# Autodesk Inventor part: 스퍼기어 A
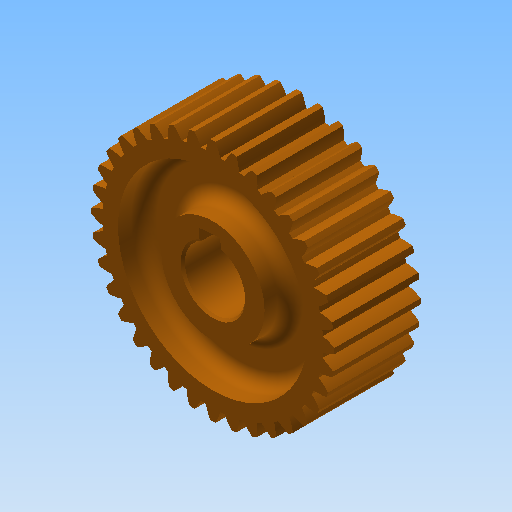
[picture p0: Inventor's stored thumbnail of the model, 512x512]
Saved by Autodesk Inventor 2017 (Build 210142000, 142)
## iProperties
Created: 2020-04
Part Number: 스퍼기어 A
Material: Steel
Document SubType Name: Modeling
Designer: mduedu
Categories: <?xml version="1.0" encoding="UTF-16"?> <MemberInstance><Categories><FamilyTemplate><FamilyTemplateParameter ValueType="xs:double" Id="1" ObjectReferenceKey="da
Density: 7.85 g/cm^3
Mass: 238.005 g
Surface Area: 130.635 cm^2
Volume: 30.3191 cm^3
Appearance: 주황색
CustomPartVersion: 1
Author: mduedu
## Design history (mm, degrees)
sketch "Sketch1"
  geometry: C1 r 28.2 at (0, 0)
  constraints: 1 centre point
  dimensions: "d0" = 56.4 diameter of C1 (= da_da)
extrude "Extrusion1" new body sketch "Sketch1" distance "d1" = 20 (= da_b); taper "d2" = 0 deg
workplane "Work Plane2"
sketch "Sketch2"
  geometry: C1 r 28.2 at (0, 0) reference; C2 r 27 at (0, 0)
  constraints: 1 centre point, 1 coincident
  dimensions: "d3" = 54 diameter of C2 (= da_dw)
feature "피치 지름" sketch "Sketch2" dims "d4" = 10, "d5" = 0
workplane "Work Plane8"
workplane "Work Plane9"
feature "스퍼 기어" dims "da_b" = 20, "da_d" = 54, "da_aw" = 45, "da_da" = 56.4, "da_df" = 51.129, "da_dw" = 54, angle "da_beta" = 0 deg, "da_lefttooth" = 0, "da_righttooth" = 0
node "작업 평면11"
sketch "스케치3"
  geometry: C1 r 12 at (0, 0); C2 r 22 at (0, 0); 1 further point
  constraints: 2 centre point, 2 coincident
  dimensions: "d49" = 24 diameter of C1; "d50" = 44 diameter of C2
extrude "돌출2" cut sketch "스케치3" distance "d51" = 6; taper "d52" = 0 deg
fillet "모깎기1" dims "d53" = 3
sketch "스케치4" dims "d17" = 0
  geometry: L1 (-3.06, 6.296)-(1.921, 6.731); L2 (1.921, 6.731)-(1.68, 9.483); L3 (1.68, 9.483)-(-3.301, 9.047); L4 (-3.301, 9.047)-(-3.06, 6.296); L5 (-3.728, 42.608)-(3.728, -42.608) reference; A1 r 7 centre (0, 0) between (-3.06, 6.296) and (1.921, 6.731); 1 further point
  constraints: 8 end point, 4 perpendicular, 2 point on circle, 1 centre point, 1 coincident
  dimensions: "d54" = 14 diameter of A1; "d63" = 16.3 dimension on A1 L3; "d64" = 5 distance of L2.end L3.end
extrude "돌출3" cut sketch "스케치4" stored distance "d58" = 6; taper "d59" = 0 deg
chamfer "모따기1" distance "d60" = 0.5; stored, may be unused: second distance "d61" = 2, angle "d62" = 45 deg
body "Solid1"
mirror "대칭1"
body "Srf1"
other parameters: "d16" = 45 (= da_aw), "d34" = 5 deg (computed from da_z), "d39" = 0, "d41" = 0, "d43" = 45 (= da_aw), "d46" = 45 (= da_aw), "d47" = 0, "d48" = 0
